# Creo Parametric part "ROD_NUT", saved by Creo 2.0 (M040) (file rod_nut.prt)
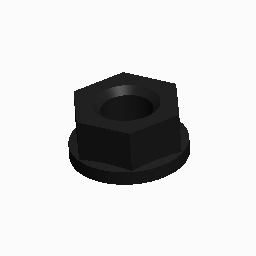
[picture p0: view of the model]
Units: millimeter Kilogram Sec (mmKs); MM, KILOGRAM, SECS

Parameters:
  MATERIAL = "35CrMo"

Created from: INLBS_PART_SOLID.PRT

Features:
  1. datum plane "SIDE", "RIGHT"
  2. datum plane "DTM1", "TOP"
  3. datum plane "DTM2", "FRONT"
  4. coordinate system "ORIGIN"
  5. datum axis "A_1"
  6. extrusion "Extrude 1", "Section 1"
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
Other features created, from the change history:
  group "COPIED_GROUP" (2 times)
  datum plane "SIDE"
  datum plane "DTM1"
  datum plane "DTM2"
  coordinate system "ORIGIN"
  revolve "Revolve 1" (2 times)
  extrusion "Extrude 1"
  extruded cut "Extrude 2"
  extruded cut "Extrude 3"
  chamfer "Chamfer 1" (2 times)
  datum point "CON_WELD"
  round "Round id 160"
  hole "Hole 1"
  datum point "CON_CAP_WELD"

Named dimensions: FLAT_D, HEX_HT, FLANGE_D, FLANGE_HT, HOLE_D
